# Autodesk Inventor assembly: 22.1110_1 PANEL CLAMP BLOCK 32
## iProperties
Created: 2007-04
Part Number: 22.1110_1 PANEL CLAMP BLOCK 32
Document SubType Name: Assembly
Designer: Andy Moles
Author: Andy Moles
